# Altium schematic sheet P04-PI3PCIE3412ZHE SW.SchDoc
size 386 x 246 mm
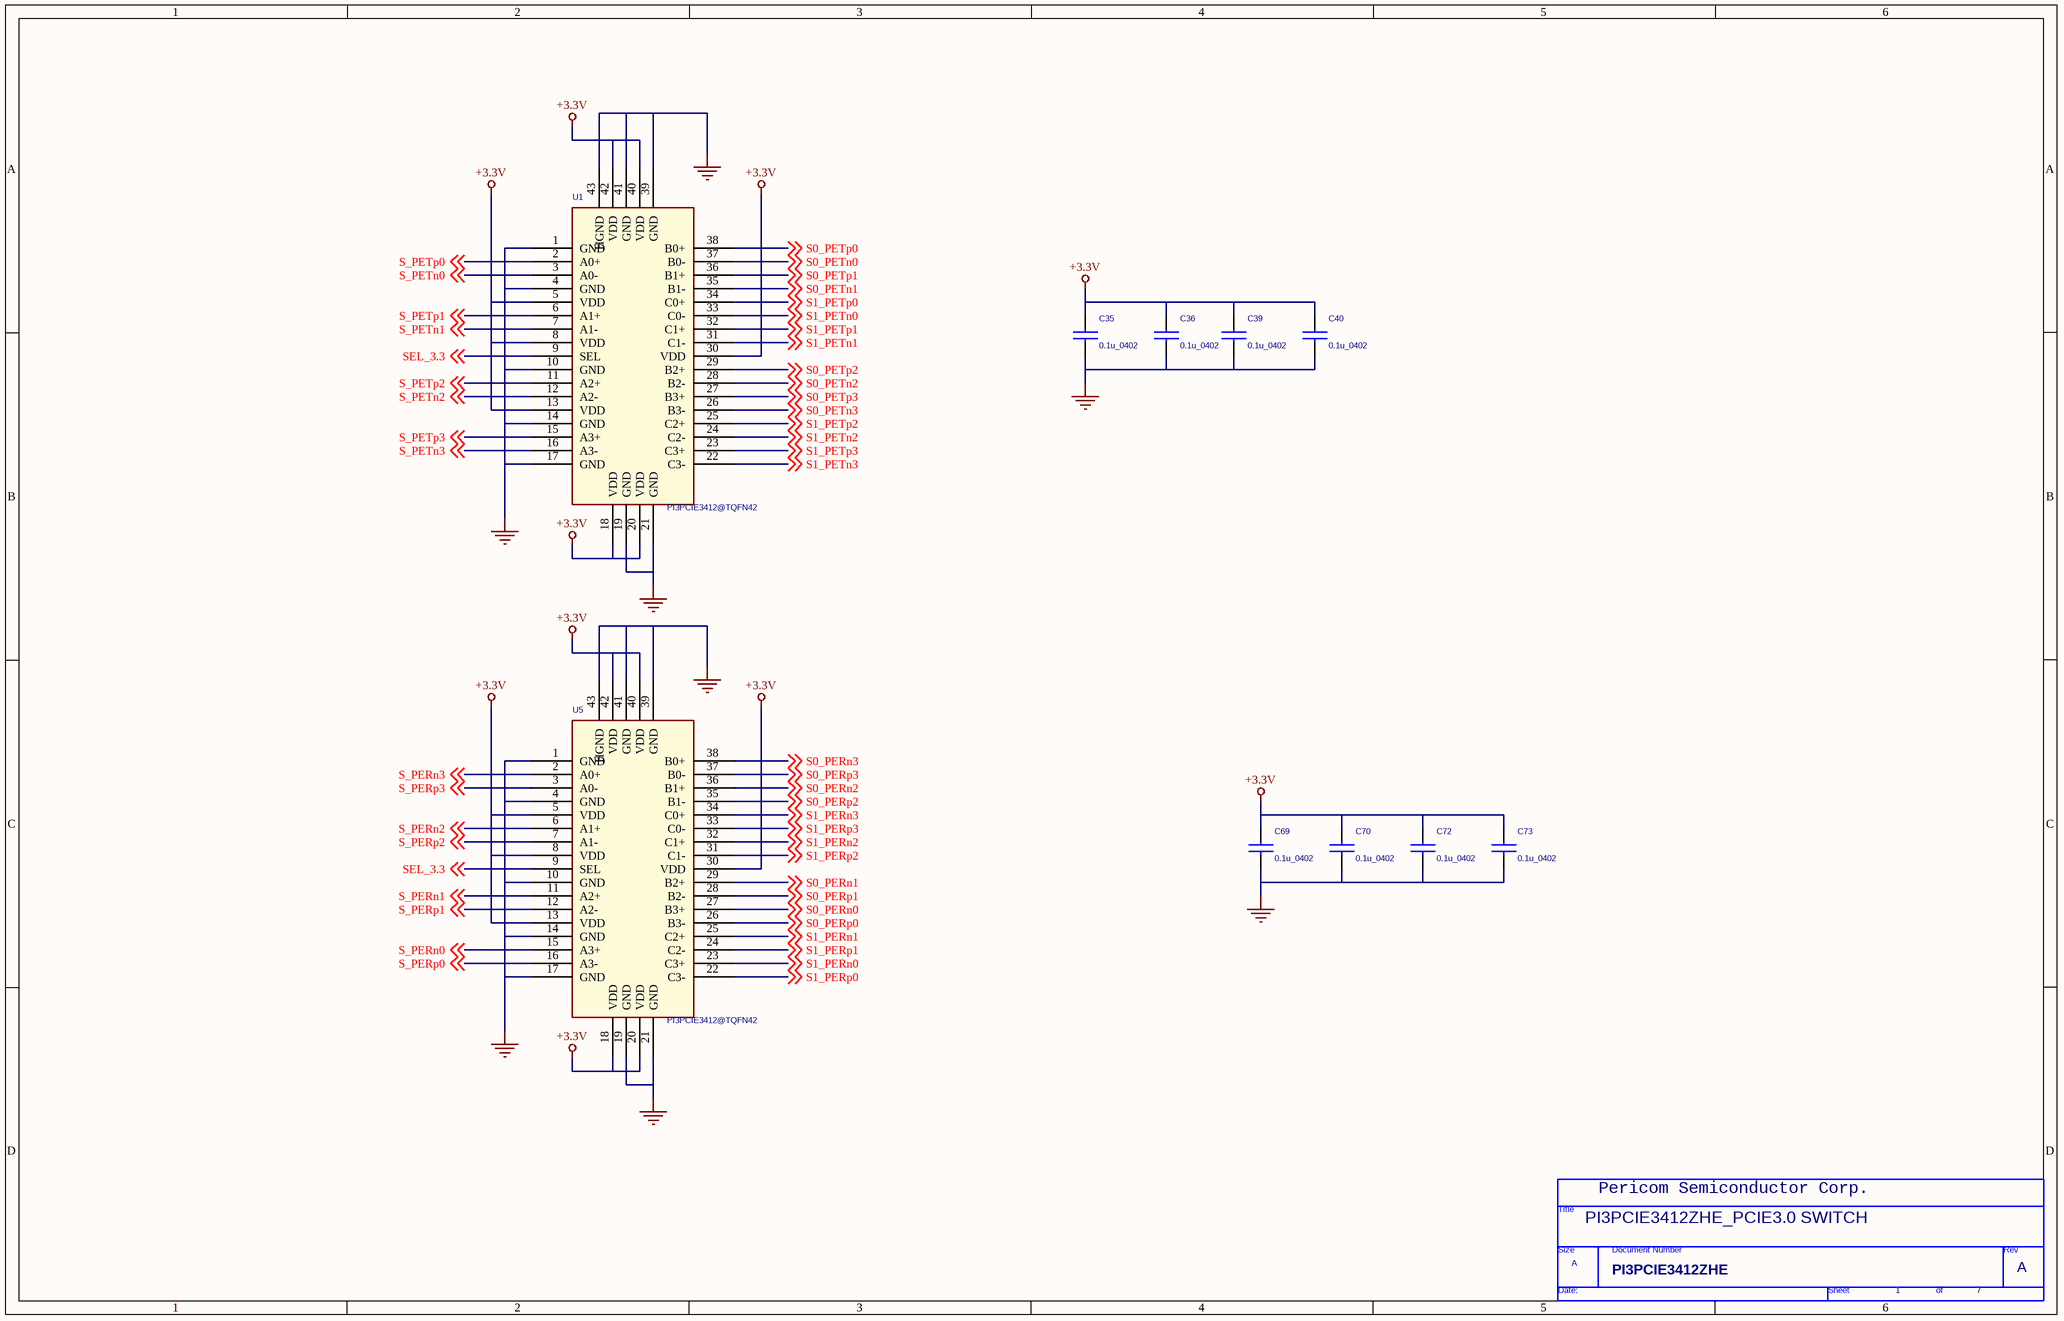
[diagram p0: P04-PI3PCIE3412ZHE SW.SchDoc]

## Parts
*  Doc: PI3PCIE3412ZHE  RevCode: A  Title: PI3PCIE3412ZHE_PCIE3.0 SWITCH  Page Number: 1  Page Count: 7  (hidden comment: TitleBlock0)  (graphical)
C35  0.1u_0402  [CC_0402]
C36  0.1u_0402  [CC_0402]
C39  0.1u_0402  [CC_0402]
C40  0.1u_0402  [CC_0402]
C69  0.1u_0402  [CC_0402]
C70  0.1u_0402  [CC_0402]
C72  0.1u_0402  [CC_0402]
C73  0.1u_0402  [CC_0402]
U1  PI3PCIE3412@TQFN42  [TQFN42]
U5  PI3PCIE3412@TQFN42  [TQFN42]

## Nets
+3.3V: C35.1 C36.1 C39.1 C40.1 C69.1 C70.1 C72.1 C73.1 U1.5(VDD) U1.8(VDD) U1.13(VDD) U1.18(VDD) U1.20(VDD) U1.30(VDD) U1.40(VDD) U1.42(VDD) U5.5(VDD) U5.8(VDD) U5.13(VDD) U5.18(VDD) U5.20(VDD) U5.30(VDD) U5.40(VDD) U5.42(VDD)
GND: C35.2 C36.2 C39.2 C40.2 C69.2 C70.2 C72.2 C73.2 U1.1(GND) U1.4(GND) U1.10(GND) U1.14(GND) U1.17(GND) U1.19(GND) U1.21(GND) U1.39(GND) U1.41(GND) U1.43(HGND) U5.1(GND) U5.4(GND) U5.10(GND) U5.14(GND) U5.17(GND) U5.19(GND) U5.21(GND) U5.39(GND) U5.41(GND) U5.43(HGND)
S0_PERn0: U5.27(B3+) ; off-sheet S0_PERn0
S0_PERn1: U5.29(B2+) ; off-sheet S0_PERn1
S0_PERn2: U5.36(B1+) ; off-sheet S0_PERn2
S0_PERn3: U5.38(B0+) ; off-sheet S0_PERn3
S0_PERp0: U5.26(B3-) ; off-sheet S0_PERp0
S0_PERp1: U5.28(B2-) ; off-sheet S0_PERp1
S0_PERp2: U5.35(B1-) ; off-sheet S0_PERp2
S0_PERp3: U5.37(B0-) ; off-sheet S0_PERp3
S0_PETn0: U1.37(B0-) ; off-sheet S0_PETn0
S0_PETn1: U1.35(B1-) ; off-sheet S0_PETn1
S0_PETn2: U1.28(B2-) ; off-sheet S0_PETn2
S0_PETn3: U1.26(B3-) ; off-sheet S0_PETn3
S0_PETp0: U1.38(B0+) ; off-sheet S0_PETp0
S0_PETp1: U1.36(B1+) ; off-sheet S0_PETp1
S0_PETp2: U1.29(B2+) ; off-sheet S0_PETp2
S0_PETp3: U1.27(B3+) ; off-sheet S0_PETp3
S1_PERn0: U5.23(C3+) ; off-sheet S1_PERn0
S1_PERn1: U5.25(C2+) ; off-sheet S1_PERn1
S1_PERn2: U5.32(C1+) ; off-sheet S1_PERn2
S1_PERn3: U5.34(C0+) ; off-sheet S1_PERn3
S1_PERp0: U5.22(C3-) ; off-sheet S1_PERp0
S1_PERp1: U5.24(C2-) ; off-sheet S1_PERp1
S1_PERp2: U5.31(C1-) ; off-sheet S1_PERp2
S1_PERp3: U5.33(C0-) ; off-sheet S1_PERp3
S1_PETn0: U1.33(C0-) ; off-sheet S1_PETn0
S1_PETn1: U1.31(C1-) ; off-sheet S1_PETn1
S1_PETn2: U1.24(C2-) ; off-sheet S1_PETn2
S1_PETn3: U1.22(C3-) ; off-sheet S1_PETn3
S1_PETp0: U1.34(C0+) ; off-sheet S1_PETp0
S1_PETp1: U1.32(C1+) ; off-sheet S1_PETp1
S1_PETp2: U1.25(C2+) ; off-sheet S1_PETp2
S1_PETp3: U1.23(C3+) ; off-sheet S1_PETp3
S_PERn0: U5.15(A3+) ; off-sheet S_PERn0
S_PERn1: U5.11(A2+) ; off-sheet S_PERn1
S_PERn2: U5.6(A1+) ; off-sheet S_PERn2
S_PERn3: U5.2(A0+) ; off-sheet S_PERn3
S_PERp0: U5.16(A3-) ; off-sheet S_PERp0
S_PERp1: U5.12(A2-) ; off-sheet S_PERp1
S_PERp2: U5.7(A1-) ; off-sheet S_PERp2
S_PERp3: U5.3(A0-) ; off-sheet S_PERp3
S_PETn0: U1.3(A0-) ; off-sheet S_PETn0
S_PETn1: U1.7(A1-) ; off-sheet S_PETn1
S_PETn2: U1.12(A2-) ; off-sheet S_PETn2
S_PETn3: U1.16(A3-) ; off-sheet S_PETn3
S_PETp0: U1.2(A0+) ; off-sheet S_PETp0
S_PETp1: U1.6(A1+) ; off-sheet S_PETp1
S_PETp2: U1.11(A2+) ; off-sheet S_PETp2
S_PETp3: U1.15(A3+) ; off-sheet S_PETp3
SEL_3.3: U1.9(SEL) U5.9(SEL) ; off-sheet SEL_3.3

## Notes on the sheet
- (near *) Pericom Semiconductor Corp.

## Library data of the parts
C35 C36 C39 C40 C69 C70 C72 C73 = C_0.1u_0402
U1 U5 = PI3PCIE3412@TQFN42_1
